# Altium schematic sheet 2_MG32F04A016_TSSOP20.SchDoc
size 330 x 228 mm
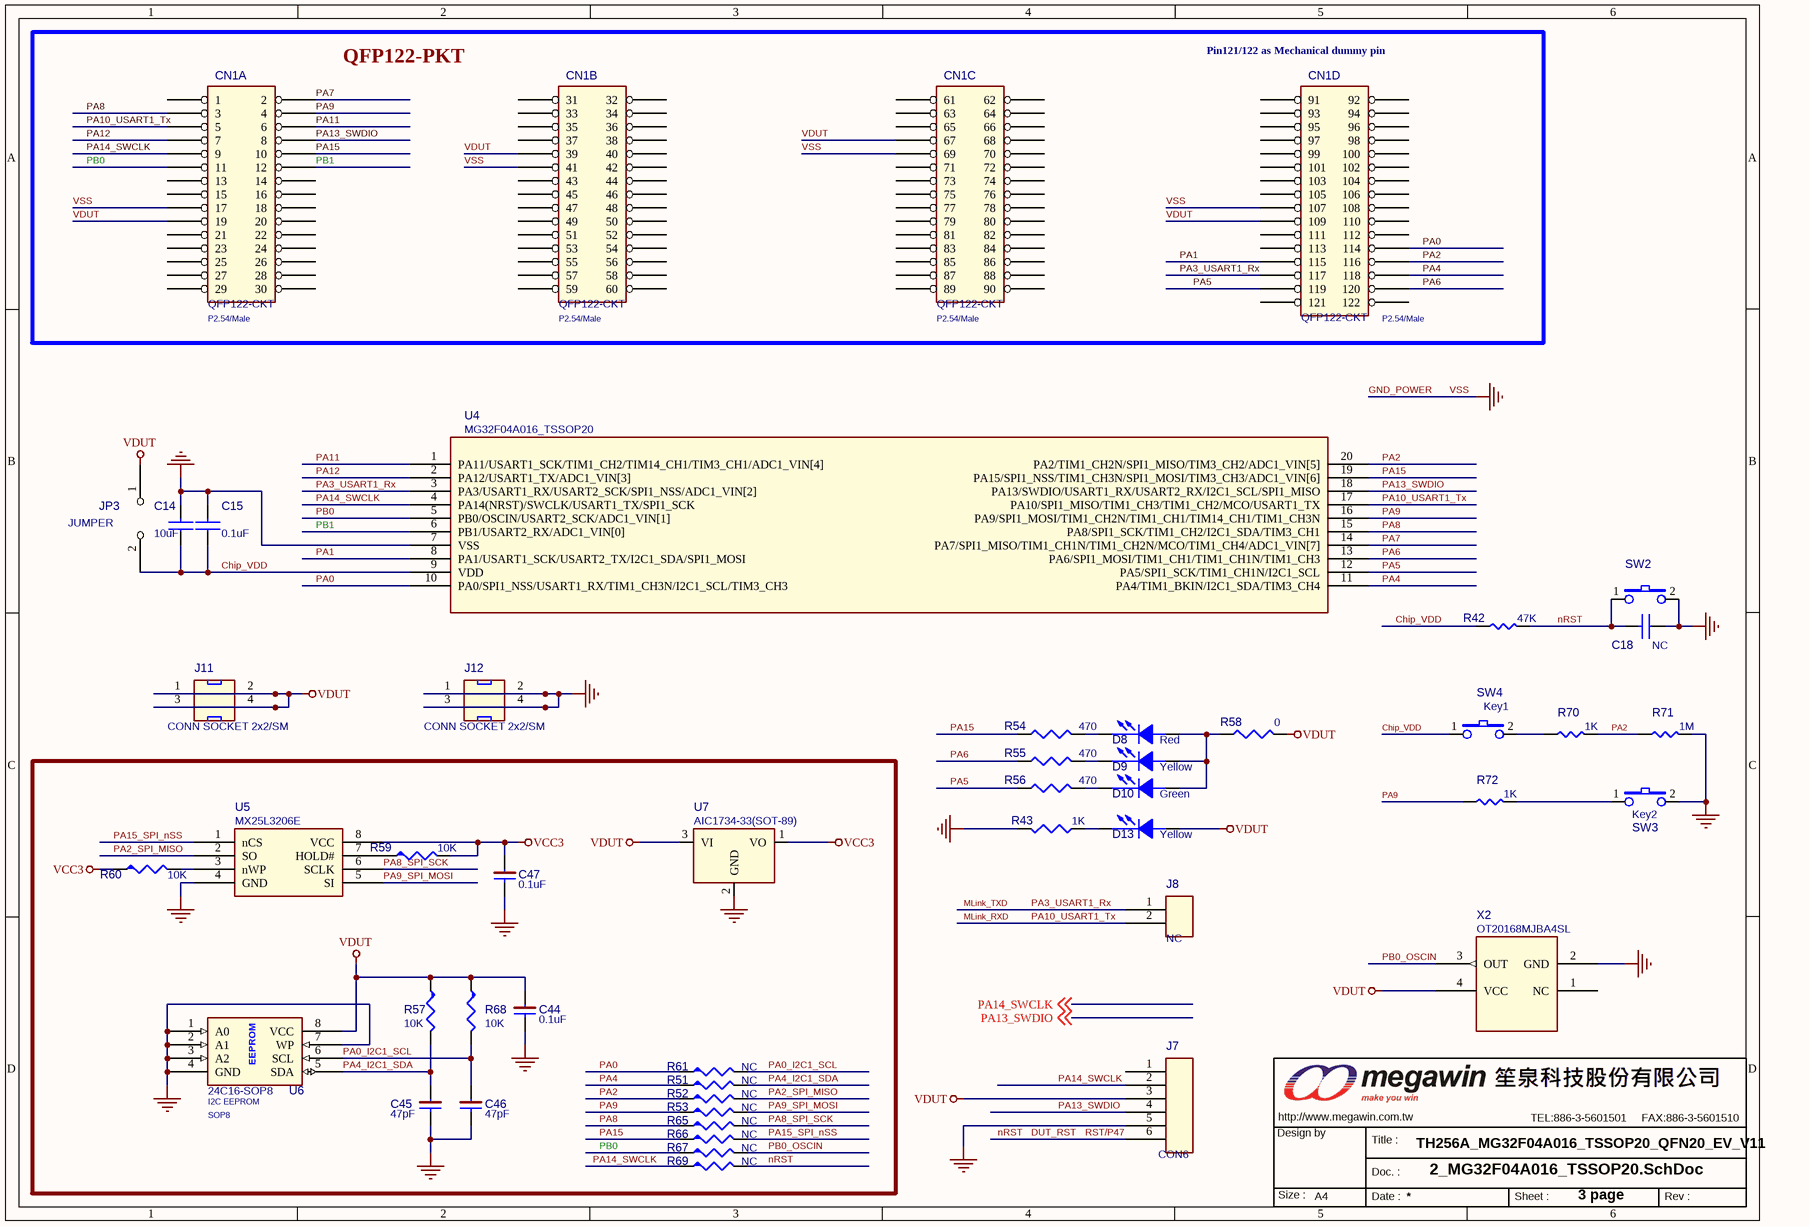
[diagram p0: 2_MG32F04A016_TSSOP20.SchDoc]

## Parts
C14  10uF  [C-0603]
C15  0.1uF  [C-0603]
C18  NC  [C-0603]
C44  0.1uF  [C-0603]
C45  47pF  [C-0603]
C46  47pF  [C-0603]
C47  0.1uF  [C-0603]
CN1  QFP122-CKT  Package: P2.54/Male  [QFP122-P2.54-CKT]  (parts A,B,C,D of 4)
D8  Red  [0805D]
D9  Yellow  [0805D]
D10  Green  [0805D]
D13  Yellow  [0805D]
J7  CON6  [PS6P254]
J8  NC  [PS2P254]
J11  CONN SOCKET 2x2/SM  [PS2X2P254]
J12  CONN SOCKET 2x2/SM  [PS2X2P254]
JP3  JUMPER  [PS2P254]
MW1  OrgAddr3: TEL:886-3-5601501     FAX:886-3-5601510  [MEGAWIN_3.4]  (hidden comment: MW-A4)  (graphical)
R42  47K  [R-0603]
R43  1K  [R-0603]
R51  NC  [R-0603]
R52  NC  [R-0603]
R53  NC  [R-0603]
R54  470  [R-0603]
R55  470  [R-0603]
R56  470  [R-0603]
R57  10K  [R-0603]
R58  0  [R-0603]
R59  10K  [R-0603]
R60  10K  [R-0603]
R61  NC  [R-0603]
R65  NC  [R-0603]
R66  NC  [R-0603]
R67  NC  [R-0603]
R68  10K  [R-0603]
R69  NC  [R-0603]
R70  1K  [R-0603]
R71  1M  [R-0603]
R72  1K  [R-0603]
SW2  SW TACT-SPST  [SW_T_2P]  (value not drawn)
SW3  Key2  [SW_T_2P]
SW4  Key1  [SW_T_2P]
U4  MG32F04A016_TSSOP20  [TSSOP20_170P065]
U5  MX25L3206E  [SO8_208P127]
U6  24C16-SOP8  Function: I2C EEPROM  Package: SOP8  [SO8_150P127]
U7  AIC1734-33(SOT-89)  [SOT89]
X2  OT20168MJBA4SL  [OSC_2.0X1.6_SMD]

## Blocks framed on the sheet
QFP122-PKT: CN1

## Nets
GND_POWER: C14.2 C15.2 C18.1 C44.2 C45.2 C46.2 C47.2 CN1.17 CN1.41 CN1.69 CN1.107 J7.5 J12.1 J12.2 J12.3 J12.4 R43.1 R71.2 SW2.2 SW3.2 U4.7(VSS) U5.4(GND) U6.1(A0) U6.2(A1) U6.3(A2) U6.4(GND) U6.7(WP) U7.2(GND) X2.2(GND)  [also labelled VSS]
VCC3: C47.1 R59.2 R60.1 U5.8(VCC) U7.1(VO)
VDUT: C44.1 CN1.19 CN1.39 CN1.67 CN1.109 D13.1(ANODE) J7.3 J11.1 J11.2 J11.3 J11.4 JP3.1 R57.1 R58.2 R68.1 U6.8(VCC) U7.3(VI) X2.4(VCC)
Chip_VDD: C14.1 C15.1 JP3.2 R42.1 SW4.1 U4.9(VDD)
DUT_RST: C18.2 J7.6 R42.2 R69.2 SW2.1  [also labelled nRST, RST/P47]
MLink_RXD: CN1.5 J8.2 U4.17(PA10/SPI1_MISO/TIM1_CH3/TIM1_CH2/MCO/USART1_TX)  [also labelled PA10_USART1_Tx]
MLink_TXD: CN1.117 J8.1 U4.3(PA3/USART1_RX/USART2_SCK/SPI1_NSS/ADC1_VIN[2])  [also labelled PA3_USART1_Rx]
PA0: CN1.114 R61.1 U4.10(PA0/SPI1_NSS/USART1_RX/TIM1_CH3N/I2C1_SCL/TIM3_CH3)
PA0_I2C1_SCL: C46.1 R61.2 R68.2 U6.6(SCL)
PA1: CN1.115 U4.8(PA1/USART1_SCK/USART2_TX/I2C1_SDA/SPI1_MOSI)
PA2: CN1.116 R52.1 R70.2 R71.1 U4.20(PA2/TIM1_CH2N/SPI1_MISO/TIM3_CH2/ADC1_VIN[5])
PA2_SPI_MISO: R52.2 U5.2(SO)
PA4: CN1.118 R51.1 U4.11(PA4/TIM1_BKIN/I2C1_SDA/TIM3_CH4)
PA4_I2C1_SDA: C45.1 R51.2 R57.2 U6.5(SDA)
PA5: CN1.119 R56.1 U4.12(PA5/SPI1_SCK/TIM1_CH1N/I2C1_SCL)
PA6: CN1.120 R55.1 U4.13(PA6/SPI1_MOSI/TIM1_CH1/TIM1_CH1N/TIM1_CH3)
PA7: CN1.2 U4.14(PA7/SPI1_MISO/TIM1_CH1N/TIM1_CH2N/MCO/TIM1_CH4/ADC1_VIN[7])
PA8: CN1.3 R65.1 U4.15(PA8/SPI1_SCK/TIM1_CH2/I2C1_SDA/TIM3_CH1)
PA8_SPI_SCK: R65.2 U5.6(SCLK)
PA9: CN1.4 R53.1 R72.1 U4.16(PA9/SPI1_MOSI/TIM1_CH2N/TIM1_CH1/TIM14_CH1/TIM1_CH3N)
PA9_SPI_MOSI: R53.2 U5.5(SI)
PA11: CN1.6 U4.1(PA11/USART1_SCK/TIM1_CH2/TIM14_CH1/TIM3_CH1/ADC1_VIN[4])
PA12: CN1.7 U4.2(PA12/USART1_TX/ADC1_VIN[3])
PA13_SWDIO: CN1.8 J7.4 U4.18(PA13/SWDIO/USART1_RX/USART2_RX/I2C1_SCL/SPI1_MISO) ; off-sheet PA13_SWDIO
PA14_SWCLK: CN1.9 J7.2 R69.1 U4.4(PA14(NRST)/SWCLK/USART1_TX/SPI1_SCK) ; off-sheet PA14_SWCLK
PA15: CN1.10 R54.1 R66.1 U4.19(PA15/SPI1_NSS/TIM1_CH3N/SPI1_MOSI/TIM3_CH3/ADC1_VIN[6])
PA15_SPI_nSS: R66.2 U5.1(nCS)
PB0: CN1.11 R67.1 U4.5(PB0/OSCIN/USART2_SCK/ADC1_VIN[1])
PB0_OSCIN: R67.2 X2.3(OUT)
PB1: CN1.12 U4.6(PB1/USART2_RX/ADC1_VIN[0])
NetD8_1: D8.1(ANODE) D9.1(ANODE) D10.1(ANODE) R58.1
NetD8_2: D8.2(CATHODE) R54.2
NetD9_2: D9.2(CATHODE) R55.2
NetD10_2: D10.2(CATHODE) R56.2
NetD13_2: D13.2(CATHODE) R43.2
NetR59_1: R59.1 U5.7(HOLD#)
NetR60_2: R60.2 U5.3(nWP)
NetR70_1: R70.1 SW4.2
NetR72_2: R72.2 SW3.1

Not connected (* = marked no-connect by the designer): CN1 1 13 14 15 16 18 20 21 22 23 24 25 26 27 28 29 30 31 32 33 34 35 36 37 38 40 42 43 44 45 46 47 48 49 50 51 52 53 54 55 56 57 58 59 60 61 62 63 64 65 66 68 70 71 72 73 74 75 76 77 78 79 80 81 82 83 84 85 86 87 88 89 90 91 92 93 94 95 96 97 98 99 100 101 102 103 104 105 106 108 110 111 112 113 121 122; J7 1; X2 1(NC)

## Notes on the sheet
- (near CN1) Pin121/122 as Mechanical dummy pin
- TH256A_MG32F04A016_TSSOP20_QFN20_EV_V11
- 3 page

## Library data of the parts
C14 C15 C18 = CAP NP_Dup1
C44 C47 = CAP-NP: 2ND PART FIELD: SMD_0805; Assembly: NC
C45 C46 = CAP-NP: Assembly: NC
D8-D10 D13 = LED
J7 = CON6_Dup1
J8 = CON2
MW1 = MW_A4_2
R42 R70-R72 = R_Dup3
R43 R54-R56 R58 = R_Dup4
R51-R53 R59-R61 R65-R67 R69 = R
R57 R68 = R: 2ND PART FIELD: SMD_0805; Assembly: NC
SW3 SW4 = SW TACT-SPST
U4 = MG32F003_TSSOP20
U6 = ICM-24CXX: 1ST PART FIELD: OSD Record Buffer; 2ND PART FIELD: SOP_8PIN; Assembly: NC
U7 = AIC1722-33
X2 = OSC8_0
